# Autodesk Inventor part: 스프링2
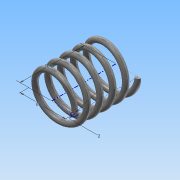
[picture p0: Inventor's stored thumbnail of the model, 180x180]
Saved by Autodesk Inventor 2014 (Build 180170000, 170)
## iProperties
Created: 2016-01
Part Number: 스프링2
Material: 강철, 탄소
Document SubType Name: Modeling
Designer: Administrator
Mass: 6.47306 g
Surface Area: 16.7315 cm^2
Volume: 0.822499 cm^3
Density: 7.87 g/cm^3
Appearance: 반연마
Author: Administrator
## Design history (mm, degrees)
sketch "스케치1"
  geometry: L1 (0, 0)-(8.5, 0); L2 (8.5, 0)-(8.5, 20.5); L3 (8.5, 20.5)-(0, 20.5); L4 (0, 20.5)-(0, 0); C1 r 1 at (8.5, 0)
  constraints: 8 end point, 2 parallel, 1 centre point, 1 coincident, 1 horizontal, 1 perpendicular
  dimensions: "d0" = 2 diameter of C1; "d1" = 17 diameter of L2 L4; "d2" = 20.5 distance of L3.end L1.start (derived)
feature "코일1" sketch "스케치1" pitch "d3" = 10; turns "d5" = 5; dims "d4" = 20.5 (= d2), "d6" = 0, angle "d7" = 90 deg, angle "d8" = 90 deg, "d9" = 0, "d10" = 0
node "작업 평면1"
sketch "스케치2"
  geometry: L1 (-9.5, 0)-(-7.5, 0) reference; 1 further point
  constraints: 1 horizontal alignment
extrude "돌출1" cut sketch "스케치2" distance "d12" = 10; taper "d13" = 0 deg
node "작업 평면2"
sketch "스케치3"
  geometry: L1 (-7.5, 0)-(-9.5, 0) reference; 1 further point
  constraints: 1 horizontal alignment
extrude "돌출2" cut sketch "스케치3" distance "d15" = 10; taper "d16" = 0 deg
node "솔리드1"
node "절단 모서리 투영1"
node "절단 모서리 투영2"
other parameters: "d11" = 20.5 (= d2), "d14" = 0
